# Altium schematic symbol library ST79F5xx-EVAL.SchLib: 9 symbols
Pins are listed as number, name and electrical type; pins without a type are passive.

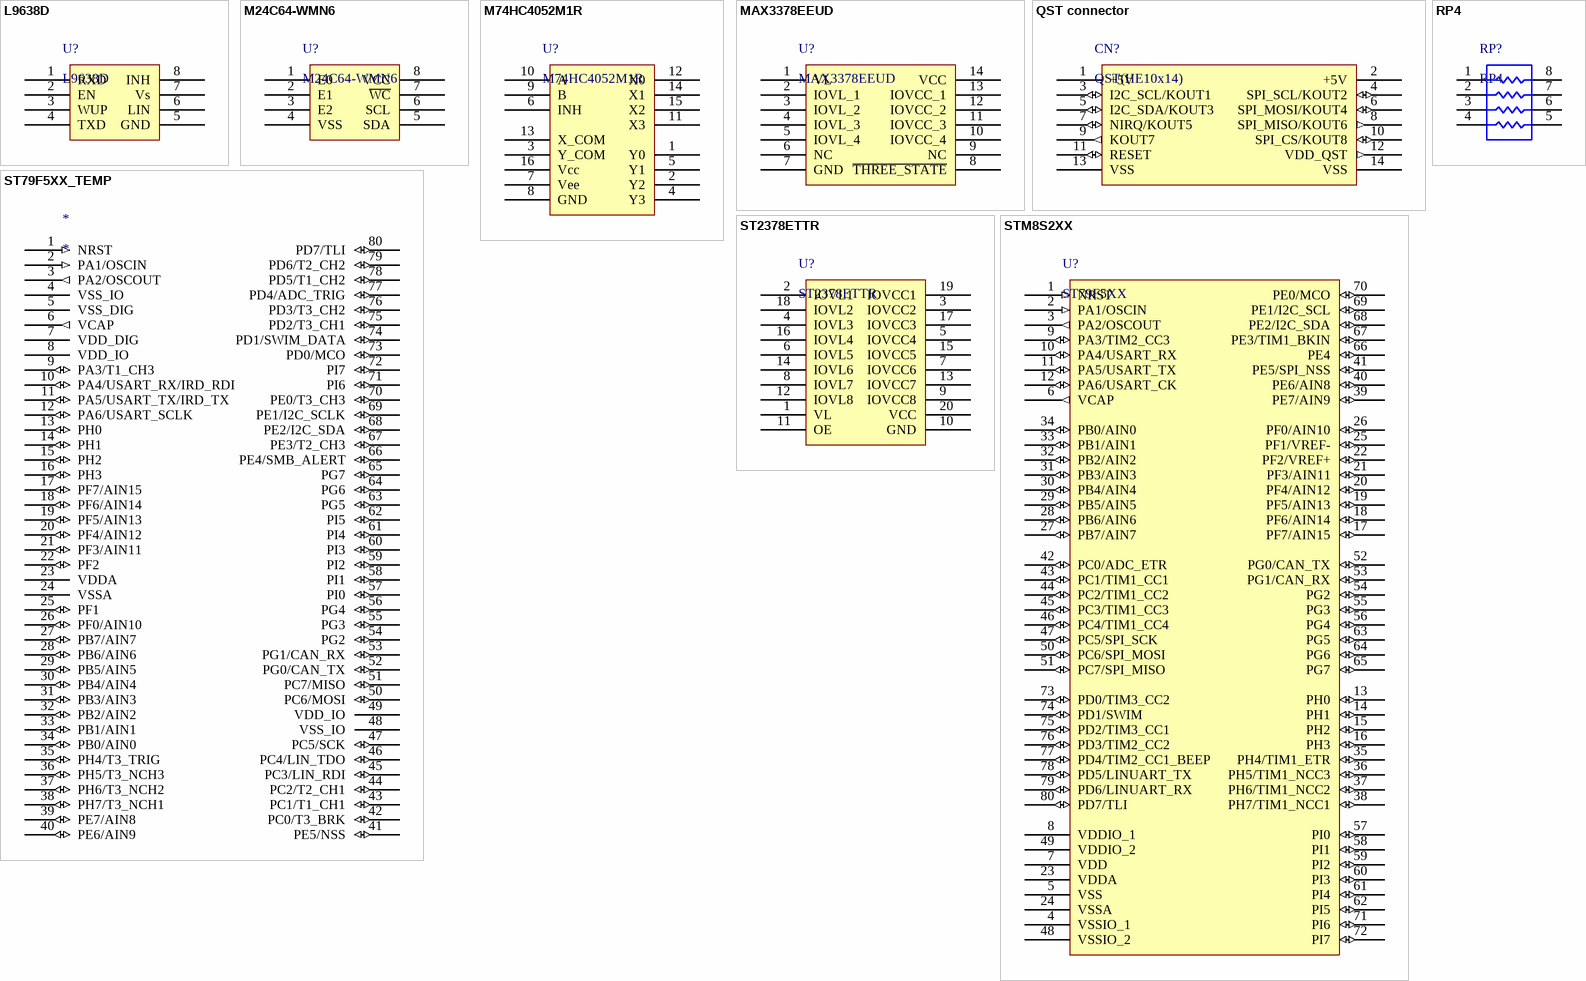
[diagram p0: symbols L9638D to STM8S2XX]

## L9638D
designator U?
footprint SO8 (Footprint not found)
pins: 1 RXD, 2 EN, 3 WUP, 4 TXD, 5 GND, 6 LIN, 7 Vs, 8 INH

## M24C64-WMN6
designator U?
footprint SO8 (Footprint not found)
pins: 1 E0, 2 E1, 3 E2, 4 VSS, 5 SDA, 6 SCL, 7 ~{WC}, 8 VCC

## M74HC4052M1R
designator U?
footprint SO16 (Footprint not found)
pins: 1 Y0, 2 Y2, 3 Y_COM, 4 Y3, 5 Y1, 6 INH, 7 Vee, 8 GND, 9 B, 10 A, 11 X3, 12 X0, 13 X_COM, 14 X1, 15 X2, 16 Vcc

## MAX3378EEUD
designator U?
footprint TSSOP14 (Footprint not found)
pins: 1 VL, 2 IOVL_1, 3 IOVL_2, 4 IOVL_3, 5 IOVL_4, 6 NC, 7 GND, 8 ~{THREE_STATE}, 9 NC, 10 IOVCC_4, 11 IOVCC_3, 12 IOVCC_2, 13 IOVCC_1, 14 VCC

## QST connector
designator CN?, comment QST(HE10x14)
pins: 1 +5V, 2 +5V, 3 I2C_SCL/KOUT1 (io), 4 SPI_SCL/KOUT2 (io), 5 I2C_SDA/KOUT3 (io), 6 SPI_MOSI/KOUT4 (io), 7 NIRQ/KOUT5 (io), 8 SPI_MISO/KOUT6 (out), 9 KOUT7 (out), 10 SPI_CS/KOUT8 (io), 11 RESET (io), 12 VDD_QST (out), 13 VSS, 14 VSS

## RP4
designator RP?
pins: 1, 2, 3, 4, 5, 6, 7, 8

## ST79F5XX_TEMP
designator *
pins: 1 NRST (in), 2 PA1/OSCIN (in), 3 PA2/OSCOUT (out), 4 VSS_IO (power), 5 VSS_DIG (power), 6 VCAP (out), 7 VDD_DIG (power), 8 VDD_IO (power), 9 PA3/T1_CH3 (io), 10 PA4/USART_RX/IRD_RDI (io), 11 PA5/USART_TX/IRD_TX (io), 12 PA6/USART_SCLK (io), 13 PH0 (io), 14 PH1 (io), 15 PH2 (io), 16 PH3 (io), 17 PF7/AIN15 (io), 18 PF6/AIN14 (io), 19 PF5/AIN13 (io), 20 PF4/AIN12 (io), 21 PF3/AIN11 (io), 22 PF2 (io), 23 VDDA (power), 24 VSSA (power), 25 PF1 (io), 26 PF0/AIN10 (io), 27 PB7/AIN7 (io), 28 PB6/AIN6 (io), 29 PB5/AIN5 (io), 30 PB4/AIN4 (io), 31 PB3/AIN3 (io), 32 PB2/AIN2 (io), 33 PB1/AIN1 (io), 34 PB0/AIN0 (io), 35 PH4/T3_TRIG (io), 36 PH5/T3_NCH3 (io), 37 PH6/T3_NCH2 (io), 38 PH7/T3_NCH1 (io), 39 PE7/AIN8 (io), 40 PE6/AIN9 (io), 41 PE5/NSS (io), 42 PC0/T3_BRK (io), 43 PC1/T1_CH1 (io), 44 PC2/T2_CH1 (io), 45 PC3/LIN_RDI (io), 46 PC4/LIN_TDO (io), 47 PC5/SCK (io), 48 VSS_IO (power), 49 VDD_IO (power), 50 PC6/MOSI (io), 51 PC7/MISO (io), 52 PG0/CAN_TX (io), 53 PG1/CAN_RX (io), 54 PG2 (io), 55 PG3 (io), 56 PG4 (io), 57 PI0 (io), 58 PI1 (io), 59 PI2 (io), 60 PI3 (io), 61 PI4 (io), 62 PI5 (io), 63 PG5 (io), 64 PG6 (io), 65 PG7 (io), 66 PE4/SMB_ALERT (io), 67 PE3/T2_CH3 (io), 68 PE2/I2C_SDA (io), 69 PE1/I2C_SCLK (io), 70 PE0/T3_CH3 (io), 71 PI6 (io), 72 PI7 (io), 73 PD0/MCO (io), 74 PD1/SWIM_DATA (io), 75 PD2/T3_CH1 (io), 76 PD3/T3_CH2 (io), 77 PD4/ADC_TRIG (io), 78 PD5/T1_CH2 (io), 79 PD6/T2_CH2 (io), 80 PD7/TLI (io)

## ST2378ETTR
designator U?
footprint TSSOP20 (Footprint not found)
pins: 1 VL, 2 IOVL1, 3 IOVCC2, 4 IOVL3, 5 IOVCC4, 6 IOVL5, 7 IOVCC6, 8 IOVL7, 9 IOVCC8, 10 GND, 11 OE, 12 IOVL8, 13 IOVCC7, 14 IOVL6, 15 IOVCC5, 16 IOVL4, 17 IOVCC3, 18 IOVL2, 19 IOVCC1, 20 VCC

## STM8S2XX
designator U?, comment ST79F5XX
footprint LQFP80 (Footprint not found)
pins: 1 NRST (in), 2 PA1/OSCIN (in), 3 PA2/OSCOUT (out), 4 VSSIO_1 (power), 5 VSS (power), 6 VCAP (out), 7 VDD (power), 8 VDDIO_1 (power), 9 PA3/TIM2_CC3 (io), 10 PA4/USART_RX (io), 11 PA5/USART_TX (io), 12 PA6/USART_CK (io), 13 PH0 (io), 14 PH1 (io), 15 PH2 (io), 16 PH3 (io), 17 PF7/AIN15 (io), 18 PF6/AIN14 (io), 19 PF5/AIN13 (io), 20 PF4/AIN12 (io), 21 PF3/AIN11 (io), 22 PF2/VREF+ (io), 23 VDDA (power), 24 VSSA (power), 25 PF1/VREF- (io), 26 PF0/AIN10 (io), 27 PB7/AIN7 (io), 28 PB6/AIN6 (io), 29 PB5/AIN5 (io), 30 PB4/AIN4 (io), 31 PB3/AIN3 (io), 32 PB2/AIN2 (io), 33 PB1/AIN1 (io), 34 PB0/AIN0 (io), 35 PH4/TIM1_ETR (io), 36 PH5/TIM1_NCC3 (io), 37 PH6/TIM1_NCC2 (io), 38 PH7/TIM1_NCC1 (io), 39 PE7/AIN9 (io), 40 PE6/AIN8 (io), 41 PE5/SPI_NSS (io), 42 PC0/ADC_ETR (io), 43 PC1/TIM1_CC1 (io), 44 PC2/TIM1_CC2 (io), 45 PC3/TIM1_CC3 (io), 46 PC4/TIM1_CC4 (io), 47 PC5/SPI_SCK (io), 48 VSSIO_2 (power), 49 VDDIO_2 (power), 50 PC6/SPI_MOSI (io), 51 PC7/SPI_MISO (io), 52 PG0/CAN_TX (io), 53 PG1/CAN_RX (io), 54 PG2 (io), 55 PG3 (io), 56 PG4 (io), 57 PI0 (io), 58 PI1 (io), 59 PI2 (io), 60 PI3 (io), 61 PI4 (io), 62 PI5 (io), 63 PG5 (io), 64 PG6 (io), 65 PG7 (io), 66 PE4 (io), 67 PE3/TIM1_BKIN (io), 68 PE2/I2C_SDA (io), 69 PE1/I2C_SCL (io), 70 PE0/MCO (io), 71 PI6 (io), 72 PI7 (io), 73 PD0/TIM3_CC2 (io), 74 PD1/SWIM (io), 75 PD2/TIM3_CC1 (io), 76 PD3/TIM2_CC2 (io), 77 PD4/TIM2_CC1_BEEP (io), 78 PD5/LINUART_TX (io), 79 PD6/LINUART_RX (io), 80 PD7/TLI (io)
